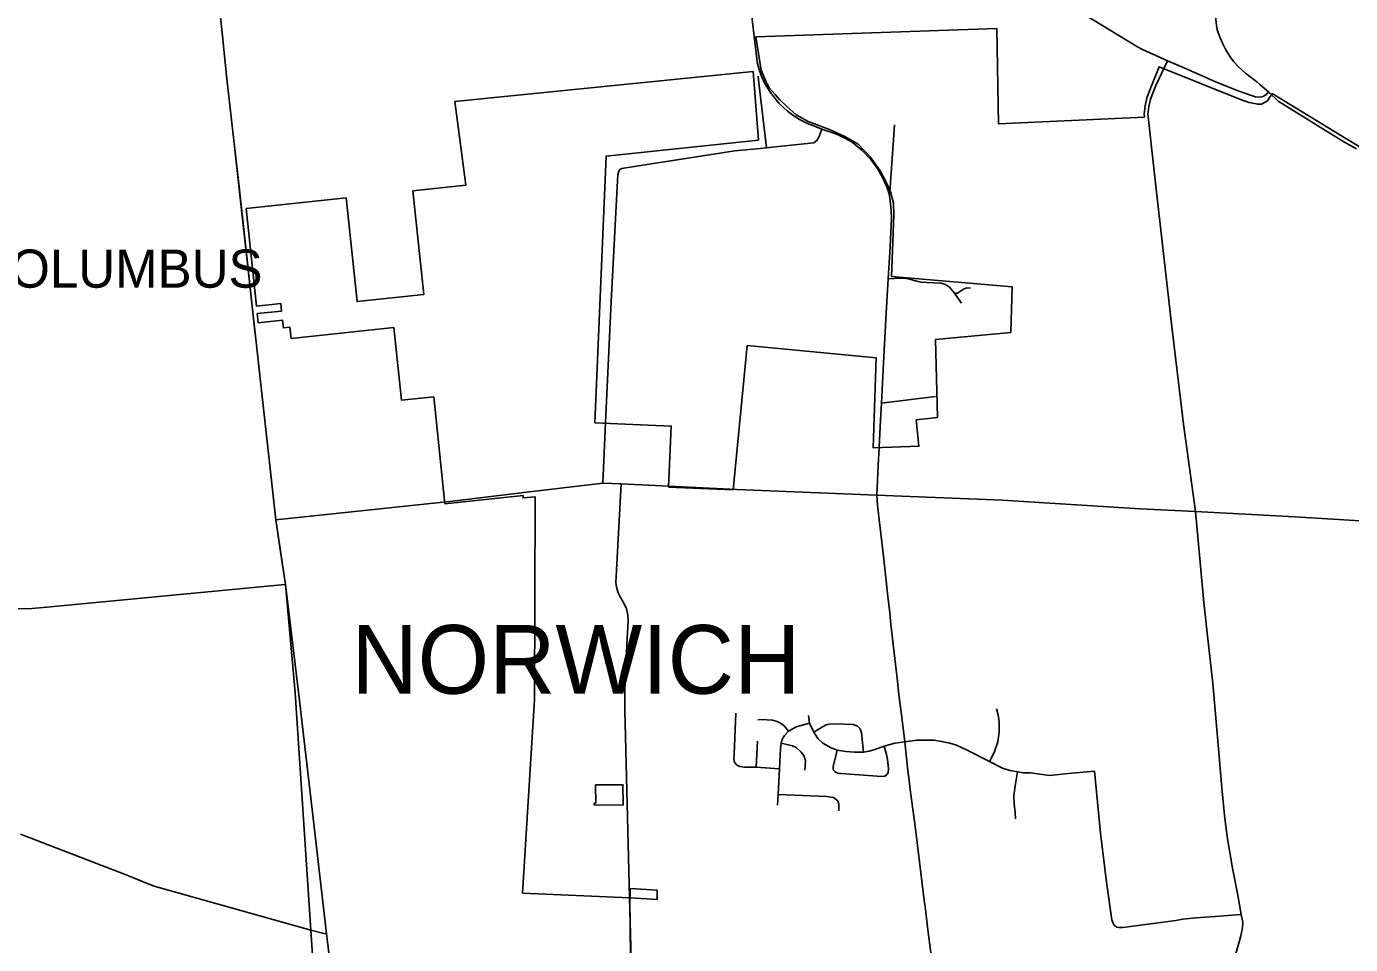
# Model space of a CAD drawing. Extents: x 1729596 to 1934326, y 644115 to 911751.
# Drawn here: x 1774170 to 1791519, y 724585 to 736619 of the extents above; entities that cross this region are included whole.
import ezdxf

# ---------------------------------------------------------------- set-up
doc = ezdxf.new("R2010")
doc.units = 0
for name, color, linetype in [('GM_X_City_Street', 7, 'Continuous'), ('GM_X_Corporation', 7, 'Continuous'), ('GM_X_Corporation_Text', 7, 'Continuous'), ('GM_X_County_Road', 7, 'Continuous'), ('GM_X_Township', 7, 'Continuous'), ('GM_X_Township_Text', 7, 'Continuous')]:
    doc.layers.add(name, color=color, linetype=linetype)

msp = doc.modelspace()

# ---------------------------------------------------------------- linework, layer by layer
at = {"layer": 'GM_X_City_Street'}
for points in [[(1790330, 735859), (1790292, 735892), (1790145, 736005), (1790050, 736089), (1789991, 736157), (1789940, 736221), (1789885, 736311), (1789842, 736402), (1789813, 736469), (1789773, 736577), (1789761, 736632), (1789673, 737452), (1789559, 738488), (1789553, 738537), (1789407, 739533), (1789344, 740018), (1789285, 740516), (1789260, 740650)], [(1783677, 739468), (1783922, 739315), (1784567, 738918), (1785211, 738522), (1786306, 737848), (1786531, 737713), (1787324, 737219), (1787916, 736848), (1788483, 736500), (1788730, 736352), (1788792, 736319), (1789122, 736169), (1789347, 736074), (1789742, 735899), (1790034, 735782), (1790159, 735738)], [(1776955, 734518), (1776883, 735163), (1776797, 735932), (1776733, 736538), (1776628, 737517)], [(1783907, 735770), (1783901, 735778), (1783851, 735862), (1783810, 735946), (1783788, 736004), (1783777, 736040), (1783749, 736133), (1783739, 736193), (1783675, 736751), (1783617, 737244), (1783594, 737433), (1783577, 737618)], [(1789944, 724200), (1790081, 724699), (1790105, 724804), (1790108, 724874), (1790088, 724979), (1790041, 725234), (1789973, 725588), (1789906, 725972), (1789873, 726237), (1789834, 726638), (1789800, 727052), (1789717, 728011), (1789660, 728513), (1789596, 729067), (1789486, 730260), (1789329, 731408), (1789178, 732680), (1789077, 733565), (1789024, 734030), (1788973, 734485), (1788914, 734998), (1788870, 735400), (1788865, 735473), (1788869, 735501), (1788878, 735571), (1788899, 735667), (1788967, 735846), (1789122, 736169)], [(1783783, 735020), (1783865, 735028), (1783762, 735918), (1783758, 735967)], [(1790451, 735756), (1790330, 735859)], [(1784475, 735320), (1784402, 735348), (1784297, 735402), (1784213, 735458), (1784143, 735509), (1784027, 735615), (1783961, 735695), (1783907, 735770)], [(1790159, 735738), (1790195, 735725), (1790275, 735697), (1790316, 735691), (1790357, 735696), (1790391, 735708), (1790451, 735756)], [(1790451, 735756), (1790572, 735640), (1791432, 735108), (1791596, 735016)], [(1783865, 735028), (1784022, 735045), (1784486, 735092), (1784527, 735123), (1784556, 735178), (1784590, 735275)], [(1784672, 735247), (1784590, 735275), (1784475, 735320)], [(1785481, 734447), (1785546, 735329)], [(1785485, 733731), (1785504, 734107), (1785502, 734208), (1785489, 734336), (1785472, 734426), (1785438, 734525), (1785387, 734639), (1785319, 734758), (1785232, 734877), (1785114, 734999), (1784988, 735101), (1784901, 735152), (1784799, 735204), (1784672, 735247)], [(1781955, 734749), (1781963, 734753), (1781972, 734758), (1782024, 734765), (1783452, 734987), (1783783, 735020)], [(1781759, 731426), (1781832, 733016), (1781917, 734679), (1781930, 734723), (1781944, 734743), (1781955, 734749)], [(1785472, 734426), (1785481, 734447)], [(1785429, 732786), (1785463, 733311), (1785485, 733731)], [(1777164, 732624), (1777065, 733519)], [(1785463, 733311), (1785626, 733320), (1785695, 733315), (1785747, 733306), (1785832, 733281), (1785896, 733267), (1785964, 733262), (1786153, 733255), (1786211, 733239), (1786263, 733204), (1786328, 733124), (1786402, 733025), (1786423, 732992)], [(1786328, 733124), (1786371, 733123), (1786449, 733175), (1786493, 733193), (1786541, 733189)], [(1785344, 731105), (1785361, 731460), (1785372, 731680), (1785398, 732206), (1785429, 732784), (1785429, 732786)], [(1777280, 731572), (1777176, 732519)], [(1785372, 731680), (1786081, 731770)], [(1781722, 730635), (1781759, 731426)], [(1777437, 730152), (1777333, 731099)], [(1785481, 728938), (1785462, 729108), (1785399, 729675), (1785340, 730193), (1785323, 730344), (1785311, 730474), (1785329, 730870), (1785343, 731097), (1785344, 731105)], [(1780654, 730505), (1781722, 730635), (1781962, 730623), (1783476, 730548), (1785311, 730474)], [(1782072, 725200), (1782025, 727132), (1782011, 727662), (1782011, 727904), (1782016, 728049), (1782039, 728595), (1782052, 728830), (1782048, 728903), (1782034, 728984), (1782010, 729034), (1781982, 729089), (1781950, 729141), (1781921, 729194), (1781903, 729270), (1781893, 729331), (1781902, 729493), (1781962, 730623)], [(1785311, 730474), (1786954, 730410), (1788762, 730295), (1789486, 730260), (1790791, 730191), (1791647, 730138), (1791657, 730138)], [(1777437, 730152), (1779548, 730374)], [(1777509, 729675), (1777437, 730152)], [(1785638, 727562), (1785638, 727565), (1785602, 727860), (1785582, 728036), (1785520, 728559), (1785493, 728824), (1785481, 728938)], [(1783473, 726942), (1783447, 726974), (1783438, 727018), (1783442, 727081), (1783466, 727619)], [(1786787, 726983), (1786850, 727104), (1786896, 727243), (1786916, 727371), (1786915, 727505), (1786903, 727598), (1786882, 727676)], [(1784156, 727383), (1784098, 727453), (1784050, 727485), (1784005, 727508), (1783944, 727527), (1783871, 727531), (1783814, 727533), (1783752, 727532)], [(1784011, 726412), (1784018, 726553), (1784035, 726887), (1784050, 727154), (1784058, 727227), (1784073, 727275), (1784101, 727327), (1784156, 727383), (1784256, 727440), (1784432, 727489)], [(1784417, 727588), (1784432, 727489), (1784485, 727367), (1784541, 727288), (1784607, 727223), (1784713, 727163), (1784793, 727134), (1784905, 727116), (1785020, 727109), (1785137, 727107), (1785214, 727119), (1785274, 727137), (1785407, 727185), (1785469, 727203), (1785548, 727223), (1785678, 727244), (1785835, 727263), (1785929, 727266), (1786058, 727263), (1786160, 727248), (1786268, 727226), (1786355, 727200), (1786505, 727130), (1786787, 726983), (1786961, 726898), (1787055, 726866), (1787155, 726848), (1787236, 726835), (1787325, 726835), (1787577, 726802), (1787866, 726833), (1788164, 726860)], [(1785137, 727107), (1785111, 727360), (1785093, 727412), (1785059, 727447), (1785003, 727469), (1784778, 727479), (1784693, 727476), (1784650, 727464), (1784600, 727438), (1784485, 727367)], [(1785725, 726822), (1785678, 727244), (1785638, 727562)], [(1783731, 726909), (1783748, 727253)], [(1784370, 726872), (1784377, 726993), (1784356, 727063), (1784319, 727107), (1784256, 727166), (1784209, 727188), (1784058, 727227)], [(1784793, 727134), (1784740, 726920), (1784739, 726876), (1784757, 726856), (1784779, 726841), (1784803, 726833), (1784842, 726826), (1785379, 726789), (1785416, 726794), (1785443, 726813), (1785461, 726837), (1785467, 726893), (1785451, 727009), (1785439, 727076), (1785407, 727185)], [(1783473, 726942), (1783516, 726918), (1783579, 726911), (1783731, 726909), (1784035, 726887)], [(1785944, 725080), (1785934, 725163), (1785829, 726034), (1785797, 726263), (1785749, 726618), (1785727, 726809), (1785725, 726822)], [(1787131, 726234), (1787123, 726318), (1787110, 726429), (1787108, 726536), (1787125, 726664), (1787155, 726848)], [(1788430, 724830), (1788414, 724854), (1788391, 724907), (1788322, 725405), (1788242, 726047), (1788164, 726860)], [(1784018, 726553), (1784656, 726527), (1784745, 726512), (1784800, 726470)], [(1784813, 726336), (1784815, 726427), (1784800, 726470)], [(1786023, 724447), (1785985, 724743), (1785944, 725080)], [(1788430, 724830), (1788453, 724811), (1788485, 724807), (1788535, 724810), (1789035, 724873), (1789230, 724902), (1789322, 724916), (1789493, 724935), (1789747, 724953), (1790088, 724979)]]:
    msp.add_lwpolyline(points, dxfattribs=at)
at = {"layer": 'GM_X_Corporation'}
msp.add_lwpolyline([(1782093, 723654), (1782076, 725199), (1780670, 725260), (1780827, 727797), (1780837, 730452), (1780678, 730440), (1780677, 730470), (1779654, 730364), (1779507, 731764), (1779085, 731719), (1778983, 732673), (1777637, 732530), (1777622, 732677), (1777536, 732668), (1777525, 732768), (1777207, 732734), (1777194, 732855), (1777513, 732889), (1777502, 732988), (1777184, 732955), (1777049, 734232), (1778358, 734372), (1778503, 733014), (1779377, 733108), (1779233, 734463), (1779925, 734537), (1779785, 735635), (1783690, 736031), (1783761, 735131), (1781764, 734921), (1781619, 731424), (1782618, 731382), (1782584, 730581), (1783429, 730546), (1783614, 732439), (1785305, 732274), (1785265, 731095), (1785864, 731116), (1785829, 731462), (1786109, 731495), (1786081, 732516), (1787068, 732606), (1787086, 733205), (1785506, 733341), (1785537, 734146), (1785530, 734302), (1785490, 734451), (1785435, 734577), (1785357, 734729), (1785223, 734911), (1785067, 735075), (1784895, 735179), (1784693, 735269), (1784413, 735373), (1784257, 735460), (1784128, 735574), (1784041, 735657), (1783980, 735727), (1783903, 735814), (1783857, 735903), (1783797, 736047), (1783729, 736484), (1786883, 736592), (1786907, 735343), (1788818, 735431), (1788815, 735475), (1788820, 735508), (1788829, 735580), (1788851, 735682), (1788920, 735864), (1789012, 736092), (1790098, 735655), (1790189, 735623), (1790305, 735599), (1790352, 735602), (1790432, 735643), (1790492, 735739), (1791458, 735151), (1791718, 734992)], dxfattribs=at)
for points in [[(1781627, 726679), (1781629, 726439), (1781609, 726439), (1781610, 726413), (1781990, 726415), (1781985, 726679)], [(1782080, 725319), (1782082, 725199), (1782435, 725176), (1782434, 725297)]]:
    msp.add_lwpolyline(points, close=True, dxfattribs=at)
at = {"layer": 'GM_X_County_Road'}
for points in [[(1777065, 733519), (1776955, 734518)], [(1777176, 732519), (1777164, 732624)], [(1777333, 731099), (1777280, 731572)], [(1779548, 730374), (1779718, 730392), (1780654, 730505)], [(1777565, 729305), (1777509, 729675)], [(1771794, 729168), (1772912, 729117), (1773134, 729105), (1773270, 729095), (1773412, 729078), (1773515, 729060), (1773633, 729037), (1773733, 729018), (1773839, 729000), (1773954, 728991), (1774076, 728987), (1774241, 728991), (1774436, 729008), (1777513, 729300)], [(1777513, 729300), (1777565, 729305)], [(1777761, 727673), (1777676, 728365), (1777565, 729305)], [(1778102, 724724), (1777991, 725673), (1777906, 726429), (1777766, 727631), (1777761, 727673)], [(1774090, 726031), (1775440, 725510), (1775595, 725449), (1775701, 725407), (1775843, 725352), (1777898, 724773), (1778050, 724736)], [(1782108, 723626), (1782105, 723813), (1782086, 724734), (1782077, 725019), (1782072, 725200)], [(1778050, 724736), (1778102, 724724)], [(1778102, 724724), (1778102, 724724), (1778122, 724551), (1778230, 723582)]]:
    msp.add_lwpolyline(points, dxfattribs=at)
at = {"layer": 'GM_X_Township'}
msp.add_lwpolyline([(1778112, 721526), (1778045, 722532), (1777898, 724773), (1777691, 727884), (1777565, 729305), (1777437, 730152), (1776883, 735163), (1776797, 735932), (1776733, 736538), (1776628, 737517), (1776406, 739489), (1776347, 739997), (1776216, 741134), (1776185, 741398), (1775388, 748700)], dxfattribs=at)

# ---------------------------------------------------------------- texts
at = {"layer": 'GM_X_Corporation_Text'}
msp.add_text('COLUMBUS', height=500, rotation=0, dxfattribs=at).set_placement((1773474, 733195))
at = {"layer": 'GM_X_Township_Text'}
msp.add_text('NORWICH', height=900, rotation=0, dxfattribs=at).set_placement((1778427, 727873))

doc.saveas('drawing.dxf')
